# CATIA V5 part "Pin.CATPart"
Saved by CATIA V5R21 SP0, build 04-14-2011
Part number: Pin
Bounding box of the stored display mesh (mm): x -15 to 15, y -15 to 15, z -50 to 0
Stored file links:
  D:\CATIA V5R21 E-RESOURCES\CATIA-V5R21\catia-v5r21-prt\c12-catia-v5r20-prt\c12-catia-v5-r20-figr-12-30\cat_v5r21_Pin.CATPart
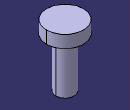
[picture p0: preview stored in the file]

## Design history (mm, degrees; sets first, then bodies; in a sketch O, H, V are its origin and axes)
Body1 (main body)
  Sketch1 on xy-plane, origin (0, 0, 0), H (1, 0, 0), V (0, 1, 0)
    circle A1 centre (0, 0) radius 15
    circle A2 centre (0, 0) radius 7.5
    radius A2 = 7.5
    radius A1 = 15
  MultiPad1: profile Sketch1, domains (length -50; length -10)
